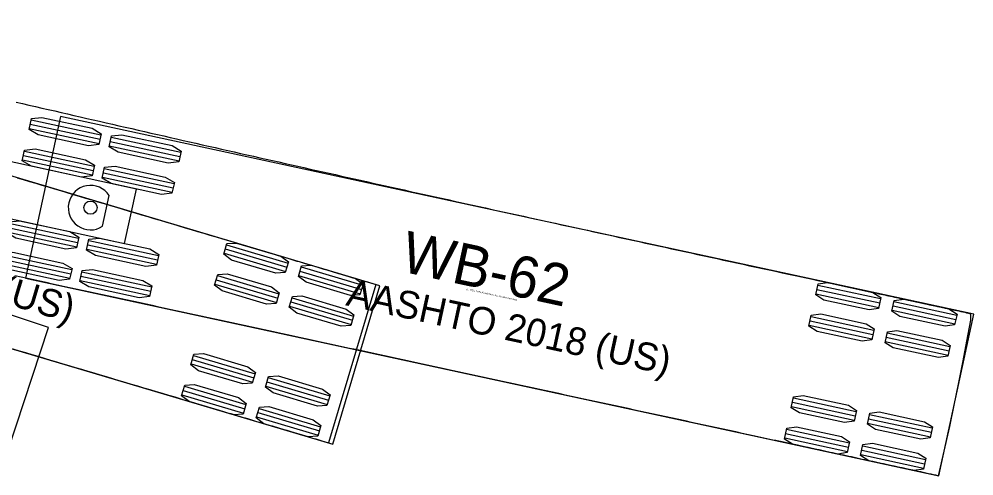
# Model space of a CAD drawing. Extents: x -14 to 1565148, y -25 to 642856.
# Drawn here: x 1565099.46 to 1565148.49, y 636493.64 to 636517.11 of the extents above; entities that cross this region are included whole.
import ezdxf

# ---------------------------------------------------------------- set-up
doc = ezdxf.new("R2010")
doc.units = 0
doc.layers.add('GE_P_Alignment_100_Stations', color=7, linetype='Continuous')
doc.layers.add('TR_Turning_Path27', color=7, linetype='Continuous')

msp = doc.modelspace()

# ---------------------------------------------------------------- linework, layer by layer
at = {"layer": 'GE_P_Alignment_100_Stations'}
for p, q in [((1565117.99, 636503.414), (1565071.987, 636517.115)), ((1565101.583, 636512.109), (1565099.784, 636503.802)), ((1565100.032, 636511.721), (1565103.616, 636510.944)), ((1565100.081, 636511.944), (1565103.664, 636511.168)), ((1565148.495, 636501.946), (1565101.583, 636512.109)), ((1565099.984, 636511.497), (1565103.567, 636510.72)), ((1565104.137, 636510.831), (1565107.721, 636510.055)), ((1565104.186, 636511.055), (1565107.769, 636510.279)), ((1565105.483, 636508.383), (1565095.123, 636510.627)), ((1565099.732, 636510.332), (1565103.315, 636509.556)), ((1565104.089, 636510.607), (1565107.672, 636509.831)), ((1565099.635, 636509.884), (1565103.218, 636509.108)), ((1565099.683, 636510.108), (1565103.267, 636509.332)), ((1565103.836, 636509.443), (1565107.42, 636508.666)), ((1565069.561, 636508.968), (1565115.564, 636495.268)), ((1565103.739, 636508.995), (1565107.323, 636508.218)), ((1565103.788, 636509.219), (1565107.371, 636508.442)), ((1565104.876, 636505.581), (1565105.483, 636508.383)), ((1565094.516, 636507.825), (1565104.876, 636505.581)), ((1565103.745, 636506.465), (1565104.088, 636508.045)), ((1565098.882, 636506.41), (1565102.466, 636505.634)), ((1565098.931, 636506.634), (1565102.514, 636505.858)), ((1565098.833, 636506.186), (1565102.417, 636505.41)), ((1565102.987, 636505.521), (1565106.57, 636504.745)), ((1565103.035, 636505.745), (1565106.619, 636504.969)), ((1565110.114, 636505.521), (1565113.276, 636504.579)), ((1565098.581, 636505.022), (1565102.165, 636504.245)), ((1565102.938, 636505.297), (1565106.522, 636504.521)), ((1565109.983, 636505.081), (1565113.146, 636504.139)), ((1565110.048, 636505.301), (1565113.211, 636504.359)), ((1565098.484, 636504.574), (1565102.068, 636503.797)), ((1565098.533, 636504.798), (1565102.116, 636504.021)), ((1565113.947, 636504.379), (1565117.11, 636503.437)), ((1565102.637, 636503.908), (1565106.221, 636503.132)), ((1565102.686, 636504.132), (1565106.269, 636503.356)), ((1565109.643, 636503.939), (1565112.805, 636502.997)), ((1565113.816, 636503.94), (1565116.979, 636502.998)), ((1565113.882, 636504.159), (1565117.045, 636503.217)), ((1565099.784, 636503.802), (1565146.695, 636493.639)), ((1565099.784, 636503.802), (1565099.784, 636503.802)), ((1565102.589, 636503.685), (1565106.172, 636502.908)), ((1565109.512, 636503.5), (1565112.675, 636502.558)), ((1565109.577, 636503.72), (1565112.74, 636502.778)), ((1565115.564, 636495.268), (1565117.99, 636503.414)), ((1565140.481, 636503.448), (1565143.706, 636502.749)), ((1565140.384, 636503), (1565143.609, 636502.301)), ((1565140.433, 636503.224), (1565143.658, 636502.525)), ((1565113.411, 636502.578), (1565116.574, 636501.636)), ((1565113.476, 636502.798), (1565116.639, 636501.856)), ((1565144.342, 636502.377), (1565147.567, 636501.678)), ((1565144.391, 636502.601), (1565147.616, 636501.902)), ((1565113.345, 636502.358), (1565116.508, 636501.416)), ((1565144.293, 636502.153), (1565147.519, 636501.454)), ((1565146.695, 636493.639), (1565148.495, 636501.946)), ((1565140.035, 636501.387), (1565143.26, 636500.689)), ((1565140.083, 636501.611), (1565143.309, 636500.913)), ((1565140.132, 636501.835), (1565143.357, 636501.137)), ((1565144.041, 636500.988), (1565147.266, 636500.29)), ((1565143.944, 636500.54), (1565147.169, 636499.842)), ((1565143.993, 636500.764), (1565147.218, 636500.066)), ((1565108.355, 636499.614), (1565111.517, 636498.673)), ((1565108.42, 636499.834), (1565111.583, 636498.892)), ((1565108.289, 636499.395), (1565111.452, 636498.453)), ((1565112.188, 636498.473), (1565115.351, 636497.531)), ((1565112.254, 636498.692), (1565115.416, 636497.75)), ((1565107.884, 636498.033), (1565111.046, 636497.091)), ((1565107.949, 636498.253), (1565111.112, 636497.311)), ((1565112.123, 636498.253), (1565115.286, 636497.311)), ((1565107.818, 636497.813), (1565110.981, 636496.872)), ((1565139.225, 636497.649), (1565142.45, 636496.95)), ((1565111.783, 636497.111), (1565114.945, 636496.169)), ((1565139.128, 636497.201), (1565142.353, 636496.502)), ((1565139.176, 636497.425), (1565142.402, 636496.726)), ((1565111.652, 636496.672), (1565114.815, 636495.73)), ((1565111.717, 636496.891), (1565114.88, 636495.949)), ((1565143.086, 636496.578), (1565146.311, 636495.879)), ((1565143.134, 636496.802), (1565146.359, 636496.103)), ((1565138.876, 636496.036), (1565142.101, 636495.338)), ((1565143.037, 636496.354), (1565146.262, 636495.655)), ((1565138.779, 636495.589), (1565142.004, 636494.89)), ((1565138.827, 636495.812), (1565142.052, 636495.114)), ((1565142.785, 636495.19), (1565146.01, 636494.491)), ((1565142.688, 636494.742), (1565145.913, 636494.043)), ((1565142.736, 636494.966), (1565145.962, 636494.267))]:
    msp.add_line(p, q, dxfattribs=at)
for points in [[(1565099.308, 636512.851), (1565099.638, 636512.774), (1565099.967, 636512.698), (1565100.297, 636512.622), (1565100.627, 636512.545), (1565100.956, 636512.469), (1565101.286, 636512.393), (1565101.615, 636512.317), (1565101.945, 636512.241), (1565102.275, 636512.165), (1565102.604, 636512.089), (1565102.934, 636512.013), (1565103.264, 636511.937), (1565103.593, 636511.862), (1565103.923, 636511.786), (1565104.253, 636511.71), (1565104.582, 636511.635), (1565104.912, 636511.559), (1565105.242, 636511.484), (1565105.571, 636511.409), (1565105.901, 636511.333), (1565106.231, 636511.258), (1565106.56, 636511.183), (1565106.89, 636511.108), (1565107.219, 636511.033), (1565107.549, 636510.958), (1565107.878, 636510.883), (1565108.207, 636510.808), (1565108.536, 636510.733), (1565108.865, 636510.659), (1565109.194, 636510.584), (1565109.523, 636510.51), (1565109.851, 636510.435), (1565110.179, 636510.361), (1565110.507, 636510.287), (1565110.835, 636510.213), (1565111.162, 636510.139), (1565111.489, 636510.065), (1565111.816, 636509.992), (1565112.142, 636509.918), (1565112.467, 636509.845), (1565112.793, 636509.772), (1565113.118, 636509.699), (1565113.442, 636509.626), (1565113.766, 636509.553), (1565114.09, 636509.481), (1565114.413, 636509.408), (1565114.736, 636509.336), (1565115.058, 636509.264), (1565115.38, 636509.192), (1565115.702, 636509.12), (1565116.024, 636509.048), (1565116.345, 636508.976), (1565116.666, 636508.904), (1565116.987, 636508.833), (1565117.307, 636508.761), (1565117.628, 636508.69), (1565117.948, 636508.618), (1565118.269, 636508.547), (1565118.589, 636508.476), (1565118.91, 636508.405), (1565119.23, 636508.333), (1565119.551, 636508.262), (1565119.872, 636508.191), (1565120.192, 636508.12), (1565120.513, 636508.049), (1565120.834, 636507.978), (1565121.156, 636507.907), (1565121.477, 636507.835), (1565121.799, 636507.764), (1565122.121, 636507.693), (1565122.443, 636507.622), (1565122.766, 636507.551), (1565123.088, 636507.479), (1565123.412, 636507.408), (1565123.735, 636507.337), (1565124.059, 636507.265), (1565124.383, 636507.194), (1565124.708, 636507.123), (1565125.033, 636507.051), (1565125.359, 636506.979), (1565125.685, 636506.908), (1565126.012, 636506.836), (1565126.339, 636506.764), (1565126.666, 636506.692), (1565126.994, 636506.62), (1565127.323, 636506.548)], [(1565099.355, 636508.964), (1565099.674, 636508.869), (1565099.994, 636508.774), (1565100.313, 636508.679), (1565100.632, 636508.583), (1565100.952, 636508.488), (1565101.271, 636508.393), (1565101.591, 636508.298), (1565101.91, 636508.203), (1565102.23, 636508.108), (1565102.549, 636508.013), (1565102.869, 636507.917), (1565103.188, 636507.822), (1565103.508, 636507.727), (1565103.827, 636507.632), (1565104.147, 636507.537), (1565104.466, 636507.442), (1565104.786, 636507.347), (1565105.105, 636507.251), (1565105.424, 636507.156), (1565105.744, 636507.061), (1565106.063, 636506.966), (1565106.383, 636506.871), (1565106.702, 636506.776), (1565107.022, 636506.681), (1565107.341, 636506.586), (1565107.661, 636506.491), (1565107.98, 636506.396), (1565108.3, 636506.301), (1565108.619, 636506.205), (1565108.939, 636506.11), (1565109.258, 636506.015), (1565109.578, 636505.92), (1565109.897, 636505.825), (1565110.217, 636505.73), (1565110.536, 636505.635), (1565110.856, 636505.539), (1565111.175, 636505.444), (1565111.494, 636505.349), (1565111.814, 636505.254), (1565112.133, 636505.159), (1565112.453, 636505.064), (1565112.559, 636505.032), (1565112.666, 636505), (1565112.772, 636504.968), (1565112.879, 636504.937), (1565112.985, 636504.905), (1565113.092, 636504.873), (1565113.198, 636504.842), (1565113.305, 636504.81), (1565113.411, 636504.778), (1565113.518, 636504.746), (1565113.624, 636504.715), (1565113.731, 636504.683), (1565113.837, 636504.651), (1565113.944, 636504.619), (1565114.05, 636504.588), (1565114.157, 636504.556), (1565114.263, 636504.524), (1565114.37, 636504.493), (1565114.476, 636504.461), (1565114.582, 636504.429), (1565114.689, 636504.397), (1565114.795, 636504.366), (1565114.902, 636504.334), (1565115.008, 636504.302), (1565115.115, 636504.27), (1565115.221, 636504.239), (1565115.328, 636504.207), (1565115.434, 636504.175), (1565115.541, 636504.144), (1565115.647, 636504.112), (1565115.754, 636504.08), (1565115.86, 636504.048), (1565115.967, 636504.017), (1565116.073, 636503.985), (1565116.18, 636503.953), (1565116.286, 636503.921), (1565116.393, 636503.89), (1565116.499, 636503.858), (1565116.606, 636503.826), (1565116.712, 636503.795), (1565116.819, 636503.763), (1565116.925, 636503.731), (1565117.032, 636503.699), (1565117.138, 636503.668), (1565117.245, 636503.636), (1565117.351, 636503.604), (1565117.458, 636503.573), (1565117.564, 636503.541), (1565117.671, 636503.509), (1565117.777, 636503.477), (1565115.351, 636495.331)], [(1565127.323, 636506.548), (1565127.652, 636506.476), (1565127.981, 636506.404), (1565128.311, 636506.332), (1565128.642, 636506.259), (1565128.973, 636506.187), (1565129.304, 636506.114), (1565129.635, 636506.042), (1565129.967, 636505.969), (1565130.3, 636505.897), (1565130.632, 636505.824), (1565130.965, 636505.751), (1565131.298, 636505.679), (1565131.631, 636505.606), (1565131.965, 636505.533), (1565132.298, 636505.461), (1565132.632, 636505.388), (1565132.966, 636505.315), (1565133.299, 636505.242), (1565133.633, 636505.17), (1565133.967, 636505.097), (1565134.301, 636505.024), (1565134.635, 636504.952), (1565134.969, 636504.879), (1565135.303, 636504.806), (1565135.637, 636504.734), (1565135.971, 636504.661), (1565136.305, 636504.589), (1565136.64, 636504.516), (1565136.974, 636504.443), (1565137.308, 636504.371), (1565137.642, 636504.298), (1565137.976, 636504.226), (1565138.31, 636504.153), (1565138.645, 636504.081), (1565138.979, 636504.008), (1565139.313, 636503.936), (1565139.647, 636503.863), (1565140.202, 636503.743), (1565140.479, 636503.683), (1565140.757, 636503.623), (1565141.034, 636503.563), (1565141.312, 636503.502), (1565141.589, 636503.442), (1565141.867, 636503.382), (1565142.145, 636503.322), (1565142.422, 636503.262), (1565142.7, 636503.202), (1565142.977, 636503.142), (1565143.255, 636503.081), (1565143.516, 636503.025), (1565143.616, 636503.003), (1565143.716, 636502.981), (1565143.817, 636502.96), (1565143.917, 636502.938), (1565144.017, 636502.916), (1565144.117, 636502.895), (1565144.218, 636502.873), (1565144.318, 636502.851), (1565144.418, 636502.829), (1565144.518, 636502.808), (1565144.618, 636502.786), (1565144.719, 636502.764), (1565144.819, 636502.743), (1565144.919, 636502.721), (1565145.019, 636502.699), (1565145.119, 636502.678), (1565145.219, 636502.656), (1565145.32, 636502.634), (1565145.42, 636502.612), (1565145.52, 636502.591), (1565145.62, 636502.569), (1565145.72, 636502.547), (1565145.82, 636502.526), (1565145.92, 636502.504), (1565146.021, 636502.482), (1565146.121, 636502.461), (1565146.221, 636502.439), (1565146.321, 636502.417), (1565146.421, 636502.396), (1565146.521, 636502.374), (1565146.621, 636502.352), (1565146.721, 636502.331), (1565146.821, 636502.309), (1565146.921, 636502.287), (1565147.021, 636502.265), (1565147.121, 636502.244), (1565147.221, 636502.222), (1565147.321, 636502.2), (1565147.421, 636502.179), (1565147.521, 636502.157), (1565147.621, 636502.135), (1565147.721, 636502.114), (1565147.821, 636502.092), (1565147.921, 636502.071), (1565148.021, 636502.049), (1565148.121, 636502.027), (1565148.221, 636502.006), (1565148.317, 636501.971), (1565148.323, 636501.642), (1565148.115, 636500.568), (1565147.918, 636499.549), (1565147.688, 636498.362), (1565147.466, 636497.268), (1565147.244, 636496.173), (1565146.955, 636494.909), (1565146.666, 636493.645)], [(1565146.666, 636493.645), (1565146.546, 636493.671), (1565146.423, 636493.698), (1565146.297, 636493.725), (1565146.166, 636493.754), (1565146.032, 636493.783), (1565145.897, 636493.812), (1565145.762, 636493.841), (1565145.626, 636493.871), (1565145.491, 636493.9), (1565145.355, 636493.929), (1565145.219, 636493.959), (1565145.083, 636493.988), (1565144.947, 636494.018), (1565144.811, 636494.047), (1565144.675, 636494.077), (1565144.539, 636494.106), (1565144.402, 636494.136), (1565144.266, 636494.165), (1565144.129, 636494.195), (1565143.992, 636494.224), (1565143.856, 636494.254), (1565143.719, 636494.283), (1565143.582, 636494.313), (1565143.445, 636494.343), (1565143.308, 636494.372), (1565143.171, 636494.402), (1565143.033, 636494.432), (1565142.896, 636494.462), (1565142.758, 636494.491), (1565142.621, 636494.521), (1565142.483, 636494.551), (1565142.345, 636494.581), (1565142.207, 636494.611), (1565142.069, 636494.641), (1565141.931, 636494.67), (1565141.793, 636494.7), (1565141.655, 636494.73), (1565141.516, 636494.76), (1565141.378, 636494.79), (1565141.239, 636494.82), (1565141.101, 636494.85), (1565140.962, 636494.88), (1565140.823, 636494.91), (1565140.684, 636494.94), (1565140.545, 636494.971), (1565140.406, 636495.001), (1565140.266, 636495.031), (1565140.127, 636495.061), (1565139.987, 636495.091), (1565139.848, 636495.121), (1565139.708, 636495.152), (1565139.568, 636495.182), (1565139.428, 636495.212), (1565139.272, 636495.246), (1565139.114, 636495.28), (1565138.956, 636495.315), (1565138.798, 636495.349), (1565138.641, 636495.383), (1565138.484, 636495.417), (1565138.328, 636495.451), (1565138.172, 636495.484), (1565138.016, 636495.518), (1565137.861, 636495.552), (1565137.705, 636495.586), (1565137.551, 636495.619), (1565137.242, 636495.686), (1565136.917, 636495.756), (1565136.592, 636495.827), (1565136.266, 636495.897), (1565135.941, 636495.968), (1565135.616, 636496.039), (1565135.291, 636496.109), (1565134.966, 636496.18), (1565134.641, 636496.25), (1565134.316, 636496.321), (1565133.991, 636496.391), (1565133.666, 636496.462), (1565133.341, 636496.532), (1565133.016, 636496.603), (1565132.691, 636496.673), (1565132.365, 636496.743), (1565132.04, 636496.814), (1565131.715, 636496.884), (1565131.391, 636496.955), (1565131.066, 636497.025), (1565130.741, 636497.095), (1565130.416, 636497.166), (1565130.091, 636497.236), (1565129.767, 636497.306), (1565129.442, 636497.377), (1565129.118, 636497.447), (1565128.794, 636497.517), (1565128.47, 636497.587), (1565128.146, 636497.657), (1565127.823, 636497.727), (1565127.5, 636497.797), (1565127.177, 636497.867), (1565126.855, 636497.937), (1565126.533, 636498.007), (1565126.211, 636498.077), (1565125.89, 636498.146), (1565125.569, 636498.216), (1565125.249, 636498.285), (1565124.929, 636498.354), (1565124.61, 636498.424), (1565124.291, 636498.493), (1565123.973, 636498.562), (1565123.655, 636498.631), (1565123.337, 636498.699), (1565123.02, 636498.768), (1565122.704, 636498.837), (1565122.387, 636498.905), (1565122.072, 636498.973), (1565121.756, 636499.042), (1565121.441, 636499.11), (1565121.127, 636499.178), (1565120.812, 636499.246), (1565120.498, 636499.314), (1565120.185, 636499.382), (1565119.871, 636499.45), (1565119.558, 636499.518), (1565119.245, 636499.586), (1565118.932, 636499.654), (1565118.619, 636499.721), (1565118.307, 636499.789), (1565117.994, 636499.857), (1565117.682, 636499.924), (1565117.37, 636499.992), (1565117.058, 636500.06), (1565116.746, 636500.127), (1565116.434, 636500.195), (1565116.122, 636500.262), (1565115.809, 636500.33), (1565115.497, 636500.398), (1565115.185, 636500.465), (1565114.872, 636500.533), (1565114.56, 636500.601), (1565114.247, 636500.669), (1565113.934, 636500.736), (1565113.62, 636500.804), (1565113.307, 636500.872), (1565112.992, 636500.94), (1565112.678, 636501.009), (1565112.363, 636501.077), (1565112.048, 636501.145), (1565111.732, 636501.213), (1565111.416, 636501.282), (1565111.1, 636501.35), (1565110.783, 636501.419), (1565110.466, 636501.488), (1565110.148, 636501.557), (1565109.83, 636501.626), (1565109.512, 636501.695), (1565109.193, 636501.764), (1565108.874, 636501.833), (1565108.554, 636501.902), (1565108.235, 636501.971), (1565107.915, 636502.04), (1565107.594, 636502.11), (1565107.274, 636502.179), (1565106.954, 636502.249), (1565106.633, 636502.318), (1565106.312, 636502.388), (1565105.991, 636502.457), (1565105.67, 636502.527), (1565105.349, 636502.596), (1565105.028, 636502.666), (1565104.707, 636502.735), (1565104.386, 636502.805), (1565104.065, 636502.875), (1565103.743, 636502.944), (1565103.422, 636503.014), (1565103.101, 636503.083), (1565102.78, 636503.153), (1565102.459, 636503.222), (1565102.137, 636503.292), (1565101.816, 636503.362), (1565101.495, 636503.431), (1565101.174, 636503.501), (1565100.853, 636503.57), (1565100.531, 636503.64), (1565100.21, 636503.71), (1565099.889, 636503.779), (1565099.568, 636503.849), (1565099.247, 636503.918)], [(1565115.351, 636495.331), (1565115.244, 636495.363), (1565115.138, 636495.394), (1565115.031, 636495.426), (1565114.925, 636495.458), (1565114.818, 636495.49), (1565114.712, 636495.521), (1565114.605, 636495.553), (1565114.499, 636495.585), (1565114.392, 636495.616), (1565114.286, 636495.648), (1565114.179, 636495.68), (1565114.073, 636495.712), (1565113.967, 636495.743), (1565113.86, 636495.775), (1565113.754, 636495.807), (1565113.647, 636495.838), (1565113.541, 636495.87), (1565113.434, 636495.902), (1565113.328, 636495.934), (1565113.221, 636495.965), (1565113.115, 636495.997), (1565113.008, 636496.029), (1565112.902, 636496.06), (1565112.795, 636496.092), (1565112.689, 636496.124), (1565112.582, 636496.156), (1565112.476, 636496.187), (1565112.369, 636496.219), (1565112.263, 636496.251), (1565112.156, 636496.282), (1565112.05, 636496.314), (1565111.943, 636496.346), (1565111.837, 636496.378), (1565111.73, 636496.409), (1565111.624, 636496.441), (1565111.517, 636496.473), (1565111.411, 636496.504), (1565111.304, 636496.536), (1565111.198, 636496.568), (1565111.091, 636496.6), (1565110.985, 636496.631), (1565110.878, 636496.663), (1565110.772, 636496.695), (1565110.665, 636496.726), (1565110.559, 636496.758), (1565110.452, 636496.79), (1565110.346, 636496.822), (1565110.239, 636496.853), (1565110.133, 636496.885), (1565110.026, 636496.917), (1565109.707, 636497.012), (1565109.388, 636497.107), (1565109.068, 636497.202), (1565108.749, 636497.297), (1565108.429, 636497.392), (1565108.11, 636497.487), (1565107.79, 636497.583), (1565107.471, 636497.678), (1565107.151, 636497.773), (1565106.832, 636497.868), (1565106.512, 636497.963), (1565106.193, 636498.058), (1565105.873, 636498.153), (1565105.554, 636498.248), (1565105.234, 636498.343), (1565104.915, 636498.438), (1565104.595, 636498.533), (1565104.276, 636498.628), (1565103.956, 636498.723), (1565103.637, 636498.818), (1565103.317, 636498.913), (1565102.998, 636499.008), (1565102.678, 636499.103), (1565102.359, 636499.198), (1565102.039, 636499.293), (1565101.72, 636499.388), (1565101.4, 636499.483), (1565101.081, 636499.578), (1565100.761, 636499.673), (1565100.442, 636499.768), (1565100.122, 636499.863), (1565099.803, 636499.957), (1565099.483, 636500.052), (1565099.163, 636500.147)]]:
    msp.add_lwpolyline(points, dxfattribs=at)
for points in [[(1565099.972, 636511.441), (1565100.093, 636512), (1565100.631, 636512.06), (1565103.211, 636511.501), (1565103.677, 636511.224), (1565103.555, 636510.665), (1565103.017, 636510.605), (1565100.437, 636511.164)], [(1565104.077, 636510.552), (1565104.198, 636511.111), (1565104.736, 636511.17), (1565107.316, 636510.612), (1565107.781, 636510.334), (1565107.66, 636509.775), (1565107.122, 636509.716), (1565104.542, 636510.275)], [(1565099.623, 636509.828), (1565099.744, 636510.387), (1565100.282, 636510.447), (1565102.862, 636509.888), (1565103.327, 636509.611), (1565103.206, 636509.052), (1565102.668, 636508.992), (1565100.088, 636509.551)], [(1565103.727, 636508.939), (1565103.848, 636509.498), (1565104.387, 636509.558), (1565106.967, 636508.999), (1565107.432, 636508.722), (1565107.311, 636508.163), (1565106.773, 636508.103), (1565104.192, 636508.662)], [(1565098.821, 636506.131), (1565098.943, 636506.69), (1565099.481, 636506.75), (1565102.061, 636506.191), (1565102.526, 636505.914), (1565102.405, 636505.354), (1565101.867, 636505.295), (1565099.287, 636505.854)], [(1565102.926, 636505.242), (1565103.047, 636505.801), (1565103.586, 636505.86), (1565106.166, 636505.301), (1565106.631, 636505.024), (1565106.51, 636504.465), (1565105.972, 636504.405), (1565103.391, 636504.964)], [(1565109.967, 636505.027), (1565110.13, 636505.575), (1565110.622, 636505.608), (1565112.899, 636504.93), (1565113.293, 636504.633), (1565113.129, 636504.085), (1565112.637, 636504.052), (1565110.36, 636504.73)], [(1565098.472, 636504.518), (1565098.593, 636505.077), (1565099.131, 636505.137), (1565101.712, 636504.578), (1565102.177, 636504.301), (1565102.056, 636503.742), (1565101.517, 636503.682), (1565098.937, 636504.241)], [(1565113.8, 636503.885), (1565113.963, 636504.433), (1565114.455, 636504.467), (1565116.733, 636503.788), (1565117.126, 636503.491), (1565116.963, 636502.943), (1565116.471, 636502.91), (1565114.194, 636503.588)], [(1565102.577, 636503.629), (1565102.698, 636504.188), (1565103.236, 636504.248), (1565105.816, 636503.689), (1565106.282, 636503.412), (1565106.16, 636502.853), (1565105.622, 636502.793), (1565103.042, 636503.352)], [(1565109.496, 636503.446), (1565109.659, 636503.994), (1565110.151, 636504.027), (1565112.428, 636503.349), (1565112.822, 636503.052), (1565112.658, 636502.504), (1565112.166, 636502.47), (1565109.889, 636503.148)], [(1565140.372, 636502.944), (1565140.493, 636503.503), (1565140.981, 636503.574), (1565143.303, 636503.071), (1565143.718, 636502.805), (1565143.597, 636502.246), (1565143.109, 636502.175), (1565140.787, 636502.678)], [(1565113.329, 636502.304), (1565113.492, 636502.852), (1565113.984, 636502.885), (1565116.262, 636502.207), (1565116.655, 636501.91), (1565116.492, 636501.362), (1565116, 636501.329), (1565113.723, 636502.007)], [(1565144.281, 636502.097), (1565144.403, 636502.656), (1565144.891, 636502.727), (1565147.213, 636502.224), (1565147.628, 636501.958), (1565147.507, 636501.399), (1565147.019, 636501.328), (1565144.696, 636501.831)], [(1565140.023, 636501.332), (1565140.144, 636501.891), (1565140.632, 636501.961), (1565142.954, 636501.458), (1565143.369, 636501.192), (1565143.248, 636500.633), (1565142.76, 636500.562), (1565140.438, 636501.066)], [(1565143.932, 636500.485), (1565144.053, 636501.044), (1565144.541, 636501.114), (1565146.863, 636500.611), (1565147.278, 636500.345), (1565147.157, 636499.786), (1565146.669, 636499.716), (1565144.347, 636500.219)], [(1565108.273, 636499.34), (1565108.436, 636499.889), (1565108.928, 636499.922), (1565111.205, 636499.244), (1565111.599, 636498.947), (1565111.436, 636498.398), (1565110.944, 636498.365), (1565108.667, 636499.043)], [(1565112.107, 636498.199), (1565112.27, 636498.747), (1565112.762, 636498.78), (1565115.039, 636498.102), (1565115.433, 636497.805), (1565115.269, 636497.257), (1565114.777, 636497.223), (1565112.5, 636497.902)], [(1565107.802, 636497.759), (1565107.965, 636498.307), (1565108.457, 636498.341), (1565110.734, 636497.662), (1565111.128, 636497.365), (1565110.965, 636496.817), (1565110.473, 636496.784), (1565108.196, 636497.462)], [(1565139.116, 636497.146), (1565139.237, 636497.705), (1565139.725, 636497.775), (1565142.047, 636497.272), (1565142.462, 636497.006), (1565142.341, 636496.447), (1565141.853, 636496.376), (1565139.531, 636496.879)], [(1565111.636, 636496.617), (1565111.799, 636497.165), (1565112.291, 636497.199), (1565114.568, 636496.521), (1565114.962, 636496.224), (1565114.798, 636495.675), (1565114.306, 636495.642), (1565112.029, 636496.32)], [(1565143.025, 636496.299), (1565143.146, 636496.858), (1565143.634, 636496.928), (1565145.956, 636496.425), (1565146.371, 636496.159), (1565146.25, 636495.6), (1565145.762, 636495.529), (1565143.44, 636496.032)], [(1565138.767, 636495.533), (1565138.888, 636496.092), (1565139.376, 636496.163), (1565141.698, 636495.66), (1565142.113, 636495.393), (1565141.992, 636494.834), (1565141.504, 636494.764), (1565139.182, 636495.267)], [(1565142.676, 636494.686), (1565142.797, 636495.245), (1565143.285, 636495.316), (1565145.607, 636494.813), (1565146.022, 636494.546), (1565145.901, 636493.987), (1565145.413, 636493.917), (1565143.091, 636494.42)]]:
    msp.add_lwpolyline(points, close=True, dxfattribs=at)
msp.add_circle((1565103.127, 636507.426), 0.34, dxfattribs=at)
msp.add_arc((1565103.127, 636507.426), 1.143, 32.7762, 302.7762, dxfattribs=at)
at = {"layer": 'TR_Turning_Path27'}
for p, q in [((1565100.976, 636501.258), (1565086.739, 636505.984)), ((1565098.455, 636493.665), (1565100.976, 636501.258)), ((1565100.976, 636501.258), (1565100.976, 636501.258))]:
    msp.add_line(p, q, dxfattribs=at)

# ---------------------------------------------------------------- texts
at = {"layer": 'GE_P_Alignment_100_Stations'}
for s, height, rotation, p in [('AASHTO 2018 (US)', 1.41667, 343.4153, (1565085.82, 636506.336)), ('WB-62', 2.125, 347.7762, (1565118.983, 636504.165)), ('AASHTO 2018 (US)', 1.41667, 347.7762, (1565116.196, 636502.413)), ('(c) 2021 Transoft Solutions, Inc. All rights reserved.', 0.085, 347.7762, (1565122.437, 636503.199))]:
    msp.add_text(s, height=height, rotation=rotation, dxfattribs=at).set_placement(p)

doc.saveas('drawing.dxf')
